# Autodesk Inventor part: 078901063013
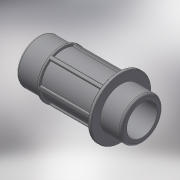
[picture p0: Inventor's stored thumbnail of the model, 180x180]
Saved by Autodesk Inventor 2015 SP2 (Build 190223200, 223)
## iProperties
Created: 2018-02
Part Number: 078901063013
Material: Generic
Description: PLASSON THREADED MALE ADAPTOR 63-1.1/4"
Document SubType Name: Modeling
Designer: KIM
Density: 1 g/cm^3
Appearance: Default
Author: KIM
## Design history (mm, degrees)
derived "078901.ipt"
feature "Solid1::078901.ipt"
tag "TaggingFeature1"
body "Solid1"
other parameters: "d4" = 2.0955, "d14" = 3.3528, "d15" = 1.6764, "d17" = 0, "d20" = 360 deg, "d40" = 22, "d41" = 41.91, "d45" = 46.101, "d46" = 29.337, "d47" = 2.2, "d77" = 111, "d78" = 63, "d85" = 0.4191, "d91" = 22.2, "d103" = 25.53, "d104" = 83, "d105" = 0.4191, "R_" = 41.91, "E_" = 83, "l_2" = 22, "l_" = 111, "d_" = 63
